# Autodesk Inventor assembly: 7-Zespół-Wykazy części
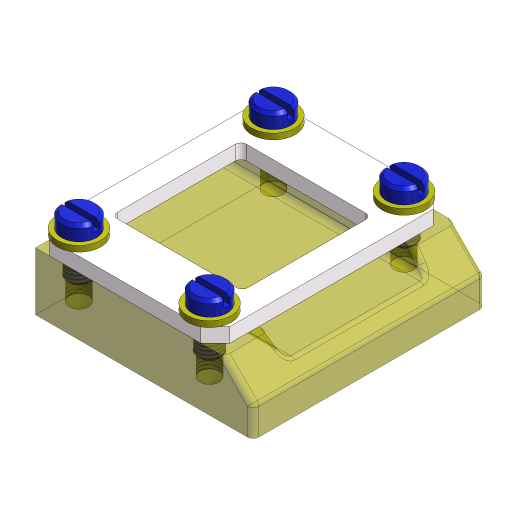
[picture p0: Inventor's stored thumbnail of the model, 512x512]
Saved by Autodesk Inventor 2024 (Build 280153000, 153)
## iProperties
Created: 2023-03
Part Number: 7-Zespół-Wykazy części
Document SubType Name: Assembly
Designer: Andrzej Jaskulski
Stock Number: 7-Zespół-Wykazy części
Mass: 113.21 g
Surface Area: 319.961 cm^2
Volume: 113.21 cm^3
Density: 1 g/cm^3
Checked By: A.J.
Engr Approved By: Andrzej Jaskulski
Mfg Approved By: Andrzej Jaskulski
Authority: A.J.
Company: ATC
Control State: 0
Master: False
Checked Out: False
Shininess: 20.0
Length Units: 11269
Angle Units: 11279
Time Units: 11290
Mass Units: 11283
Length Display Precision: 3
Angle Display Precision: 2
Compacted: True
Density: 0.0
Volumn: 0.0
Area: 0.0
PropertySet Name: Model Information
Title: A.J.: Kurs R2024-MEP
Author: Andrzej Jaskulski
Revision Number: 1/24
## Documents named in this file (3)
- C:\Users\AndJas\Documents\R2024-MEP\Obszar roboczy\7-Zespół-Wykazy części.iam
- C:\Users\AndJas\Documents\R2024-MEP\Obszar roboczy\P.ipt
- C:\Users\AndJas\Documents\R2024-MEP\Obszar roboczy\Mocowanie.iam
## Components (2 placed, 2 different names)
1. Płyta — Wstaw:1, Wstaw:2
2. Mocowanie:1 [sub-assembly] — Wstaw:1, Wstaw:2
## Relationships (2: Insert 2)
- Wstaw:1 [Insert]: Płyta ↔ Mocowanie:1
- Wstaw:2 [Insert]: Płyta ↔ Mocowanie:1
